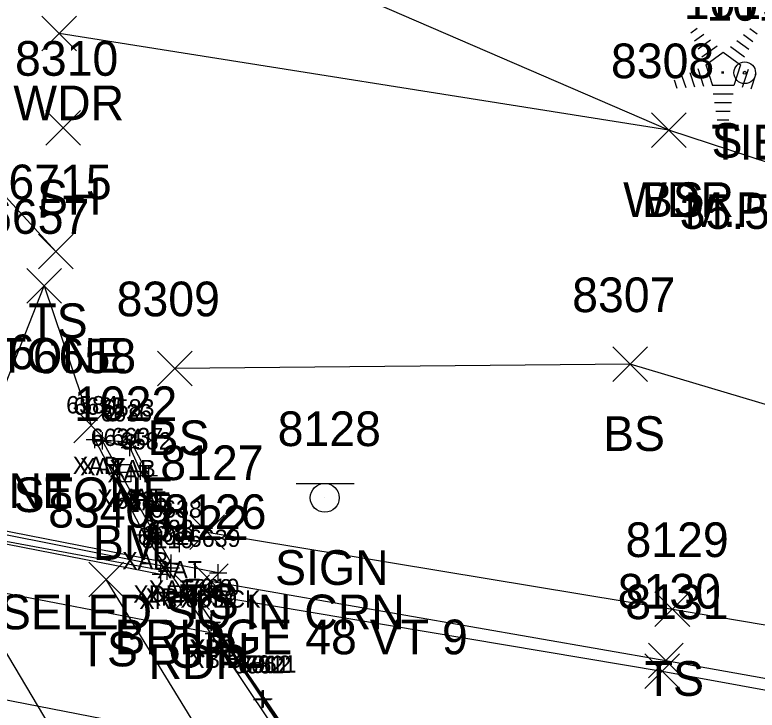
# Model space of a CAD drawing. Extents: x 1588028 to 1589597, y 137576 to 138176.
# Drawn here: x 1588943.52 to 1588986.3, y 137864.66 to 137904.74 of the extents above; entities that cross this region are included whole.
import ezdxf

# ---------------------------------------------------------------- set-up
doc = ezdxf.new("R2010")
doc.units = 0
for name, color, linetype in [('B_A', 7, 'Continuous'), ('B_I', 7, 'Continuous'), ('B_TIC', 7, 'Continuous'), ('BB', 7, 'Continuous'), ('BELB', 7, 'Continuous'), ('BR', 7, 'Continuous'), ('BSE', 7, 'Continuous'), ('BSUBM', 7, 'Continuous'), ('C_A', 7, 'Continuous'), ('C_C', 7, 'Continuous'), ('C_I', 7, 'Continuous'), ('CBP', 7, 'Continuous'), ('CPBM', 7, 'Continuous'), ('L_A', 7, 'Continuous'), ('L_C', 7, 'Continuous'), ('L_I', 7, 'Continuous'), ('L_TIC', 7, 'Continuous'), ('LASF', 7, 'Continuous'), ('LAWA', 7, 'Continuous'), ('LELB', 7, 'Continuous'), ('LTC', 7, 'Continuous'), ('P_A', 7, 'Continuous'), ('P_I', 7, 'Continuous'), ('P_TIC', 7, 'Continuous'), ('PET', 7, 'Continuous'), ('R_A', 7, 'Continuous'), ('R_I', 7, 'Continuous'), ('R_TIC', 7, 'Continuous'), ('RGR', 7, 'Continuous'), ('S_A', 7, 'Continuous'), ('S_C', 7, 'Continuous'), ('S_I', 7, 'Continuous'), ('SSGN', 7, 'Continuous')]:
    doc.layers.add(name, color=color, linetype=linetype)

msp = doc.modelspace()

# ---------------------------------------------------------------- linework, layer by layer
at = {"layer": 'B_TIC'}
for p, q in [((1588948.14, 137880.267), (1588948.215, 137880.267)), ((1588948.581, 137880.188), (1588948.656, 137880.188)), ((1588950.162, 137879.799), (1588950.238, 137879.799)), ((1588950.248, 137880.086), (1588950.324, 137880.086)), ((1588949.573, 137878.389), (1588949.648, 137878.389)), ((1588950.768, 137878.431), (1588950.843, 137878.431)), ((1588951.243, 137878.184), (1588951.319, 137878.184)), ((1588950.994, 137874.773), (1588951.069, 137874.773)), ((1588953.007, 137874.259), (1588953.083, 137874.259)), ((1588952.54, 137873.137), (1588952.615, 137873.137)), ((1588952.303, 137872.682), (1588952.378, 137872.682)), ((1588952.515, 137872.865), (1588952.59, 137872.865)), ((1588955.234, 137872.573), (1588955.31, 137872.573)), ((1588951.934, 137872.493), (1588952.009, 137872.493)), ((1588954.832, 137869.716), (1588954.907, 137869.716)), ((1588954.882, 137869.737), (1588954.958, 137869.737)), ((1588954.995, 137869.089), (1588955.071, 137869.089)), ((1588957.777, 137865.279), (1588957.853, 137865.279)), ((1588957.804, 137865.297), (1588957.879, 137865.297)), ((1588957.828, 137865.308), (1588957.903, 137865.308)), ((1588957.85, 137865.324), (1588957.926, 137865.324))]:
    msp.add_line(p, q, dxfattribs=at)
for points in [[(1588948.136, 137879.767), (1588948.136, 137880.767)], [(1588948.577, 137879.688), (1588948.577, 137880.688)], [(1588947.636, 137880.267), (1588948.636, 137880.267)], [(1588950.159, 137879.299), (1588950.159, 137880.299)], [(1588950.245, 137879.586), (1588950.245, 137880.586)], [(1588948.077, 137880.188), (1588949.077, 137880.188)], [(1588949.659, 137879.799), (1588950.659, 137879.799)], [(1588949.745, 137880.086), (1588950.745, 137880.086)], [(1588950.764, 137877.931), (1588950.764, 137878.931)], [(1588949.569, 137877.889), (1588949.569, 137878.889)], [(1588951.24, 137877.684), (1588951.24, 137878.684)], [(1588949.069, 137878.389), (1588950.069, 137878.389)], [(1588950.264, 137878.431), (1588951.264, 137878.431)], [(1588950.74, 137878.184), (1588951.74, 137878.184)], [(1588950.99, 137874.273), (1588950.99, 137875.273)], [(1588950.49, 137874.773), (1588951.49, 137874.773)], [(1588953.004, 137873.759), (1588953.004, 137874.759)], [(1588952.504, 137874.259), (1588953.504, 137874.259)], [(1588952.536, 137872.637), (1588952.536, 137873.637)], [(1588951.93, 137871.993), (1588951.93, 137872.993)], [(1588952.036, 137873.137), (1588953.036, 137873.137)], [(1588952.299, 137872.182), (1588952.299, 137873.182)], [(1588952.511, 137872.365), (1588952.511, 137873.365)], [(1588955.231, 137872.073), (1588955.231, 137873.073)], [(1588951.799, 137872.682), (1588952.799, 137872.682)], [(1588952.011, 137872.865), (1588953.011, 137872.865)], [(1588954.731, 137872.573), (1588955.731, 137872.573)], [(1588951.43, 137872.493), (1588952.43, 137872.493)], [(1588954.828, 137869.216), (1588954.828, 137870.216)], [(1588954.879, 137869.237), (1588954.879, 137870.237)], [(1588954.328, 137869.716), (1588955.328, 137869.716)], [(1588954.379, 137869.737), (1588955.379, 137869.737)], [(1588954.992, 137868.589), (1588954.992, 137869.589)], [(1588954.492, 137869.089), (1588955.492, 137869.089)], [(1588957.774, 137864.779), (1588957.774, 137865.779)], [(1588957.8, 137864.797), (1588957.8, 137865.797)], [(1588957.824, 137864.808), (1588957.824, 137865.808)], [(1588957.847, 137864.824), (1588957.847, 137865.824)], [(1588957.274, 137865.279), (1588958.274, 137865.279)], [(1588957.3, 137865.297), (1588958.3, 137865.297)], [(1588957.324, 137865.308), (1588958.324, 137865.308)], [(1588957.347, 137865.324), (1588958.347, 137865.324)]]:
    msp.add_lwpolyline(points, dxfattribs=at)
at = {"layer": 'BB'}
for points in [[(1588954.992, 137869.089), (1588908.241, 137878.076)], [(1588959.799, 137861.973), (1588912.85, 137871.124)]]:
    msp.add_lwpolyline(points, dxfattribs=at)
at = {"layer": 'BELB'}
for points in [[(1588955.231, 137872.573), (1588902.634, 137882.887)], [(1588952.511, 137872.865), (1588903.559, 137882.636)]]:
    msp.add_lwpolyline(points, dxfattribs=at)
at = {"layer": 'BR'}
for points in [[(1588903.078, 137882.159), (1588924.609, 137877.821), (1588952.299, 137872.682)], [(1588905.255, 137881.675), (1588928.151, 137877.145), (1588951.93, 137872.493)]]:
    msp.add_lwpolyline(points, dxfattribs=at)
at = {"layer": 'BSE'}
for points in [[(1588954.879, 137869.737), (1588954.828, 137869.716)], [(1588954.828, 137869.716), (1588957.8, 137865.297), (1588957.774, 137865.279), (1588962.554, 137858.252), (1588962.529, 137858.2), (1588967.182, 137851.34), (1588967.162, 137851.326), (1588971.838, 137844.422), (1588971.841, 137844.377), (1588975.126, 137839.692)], [(1588954.879, 137869.737), (1588957.847, 137865.324), (1588957.824, 137865.308), (1588962.604, 137858.282), (1588962.578, 137858.229), (1588967.235, 137851.37), (1588967.22, 137851.341), (1588971.884, 137844.455), (1588971.901, 137844.414), (1588975.167, 137839.727)]]:
    msp.add_lwpolyline(points, dxfattribs=at)
at = {"layer": 'BSUBM'}
for points in [[(1588951.24, 137878.184), (1588950.245, 137880.086), (1588948.136, 137880.267), (1588950.99, 137874.773), (1588976.922, 137836.077), (1588981.762, 137829.017), (1588983.919, 137829.058), (1588980.935, 137832.981)], [(1588952.536, 137873.137), (1588949.569, 137878.389), (1588948.577, 137880.188), (1588950.159, 137879.799), (1588950.764, 137878.431), (1588953.004, 137874.259)]]:
    msp.add_lwpolyline(points, dxfattribs=at)
at = {"layer": 'CBP'}
for radius in [0.625, 0.0833]:
    msp.add_circle((1588985.581, 137901.401), radius, dxfattribs=at)
at = {"layer": 'CPBM'}
for p, q in [((1588949.203, 137877.821), (1588949.203, 137878.821)), ((1588949.203, 137878.821), (1588950.203, 137878.821)), ((1588950.203, 137878.821), (1588950.203, 137877.821)), ((1588949.705, 137878.322), (1588949.705, 137878.322)), ((1588949.705, 137878.322), (1588949.705, 137878.322)), ((1588950.203, 137877.821), (1588949.203, 137877.821))]:
    msp.add_line(p, q, dxfattribs=at)
at = {"layer": 'L_TIC'}
for points in [[(1588945.071, 137902.665), (1588947.071, 137904.665)], [(1588947.071, 137902.665), (1588945.071, 137904.665)], [(1588945.314, 137897.227), (1588947.314, 137899.227)], [(1588947.314, 137897.227), (1588945.314, 137899.227)], [(1588980.214, 137897.085), (1588982.214, 137899.085)], [(1588982.214, 137897.085), (1588980.214, 137899.085)], [(1588980.214, 137897.085), (1588982.214, 137899.085)], [(1588982.214, 137897.085), (1588980.214, 137899.085)], [(1588944.892, 137890.105), (1588946.892, 137892.105)], [(1588946.892, 137890.105), (1588944.892, 137892.105)], [(1588944.219, 137888.116), (1588946.219, 137890.116)], [(1588946.219, 137888.116), (1588944.219, 137890.116)], [(1588951.736, 137883.363), (1588953.736, 137885.363)], [(1588953.736, 137883.363), (1588951.736, 137885.363)], [(1588977.979, 137883.602), (1588979.979, 137885.602)], [(1588979.979, 137883.602), (1588977.979, 137885.602)], [(1588946.914, 137880.079), (1588948.914, 137882.079)], [(1588948.914, 137880.079), (1588946.914, 137882.079)], [(1588953.599, 137873.922), (1588955.599, 137875.922)], [(1588955.599, 137873.922), (1588953.599, 137875.922)], [(1588947.788, 137871.187), (1588949.788, 137873.187)], [(1588949.788, 137871.187), (1588947.788, 137873.187)], [(1588980.412, 137869.487), (1588982.412, 137871.487)], [(1588982.412, 137869.487), (1588980.412, 137871.487)]]:
    msp.add_lwpolyline(points, dxfattribs=at)
at = {"layer": 'LASF'}
for points in [[(1588938.518, 137875.567), (1588942.12, 137881.309), (1588945.219, 137889.116), (1588947.914, 137881.079)], [(1588956.515, 137845.255), (1588938.518, 137875.567)]]:
    msp.add_lwpolyline(points, dxfattribs=at)
at = {"layer": 'LAWA'}
msp.add_lwpolyline([(1588979.127, 137929.799), (1588992.376, 137923.417), (1589010.557, 137910.152), (1589033.478, 137893.69), (1589028.708, 137887.383), (1589019.115, 137885.668), (1588981.214, 137898.085), (1588946.071, 137903.665)], dxfattribs=at)
at = {"layer": 'LELB'}
for points in [[(1588981.214, 137898.085), (1588942.509, 137914.83)], [(1588945.892, 137891.105), (1588931.552, 137906.749)], [(1589071.748, 137862.393), (1589034.865, 137870.653), (1589008.968, 137875.68), (1588978.979, 137884.602), (1588952.736, 137884.363)], [(1588954.599, 137874.922), (1588981.412, 137870.487), (1589021.847, 137863.644), (1589055.492, 137857.051), (1589090.034, 137851.347)], [(1588969.629, 137838.193), (1588948.788, 137872.187)]]:
    msp.add_lwpolyline(points, dxfattribs=at)
at = {"layer": 'LTC'}
for p, q in [((1588982.48, 137903.709), (1588982.835, 137903.967)), ((1588985.879, 137903.95), (1588986.298, 137903.645)), ((1588982.69, 137903.244), (1588983.219, 137903.628)), ((1588985.507, 137903.601), (1588986.057, 137903.202)), ((1588982.899, 137902.778), (1588983.603, 137903.289)), ((1588983.109, 137902.312), (1588983.987, 137902.95)), ((1588984.765, 137902.905), (1588985.575, 137902.316)), ((1588985.136, 137903.253), (1588985.816, 137902.759)), ((1588983.334, 137901.857), (1588984.345, 137902.592)), ((1588984.345, 137902.592), (1588985.342, 137901.867)), ((1588982.879, 137901.638), (1588983.21, 137900.619)), ((1588983.334, 137901.857), (1588983.721, 137900.664)), ((1588985.342, 137901.867), (1588984.951, 137900.664)), ((1588981.968, 137901.205), (1588982.18, 137900.554)), ((1588982.424, 137901.422), (1588982.695, 137900.586)), ((1588985.78, 137901.596), (1588985.442, 137900.556)), ((1588986.224, 137901.346), (1588985.937, 137900.461)), ((1588981.513, 137900.989), (1588981.665, 137900.521)), ((1588984.951, 137900.664), (1588983.721, 137900.664)), ((1588984.913, 137900.164), (1588983.768, 137900.164)), ((1588984.829, 137899.664), (1588983.841, 137899.664)), ((1588984.745, 137899.164), (1588983.914, 137899.164)), ((1588984.661, 137898.664), (1588983.986, 137898.664))]:
    msp.add_line(p, q, dxfattribs=at)
at = {"layer": 'P_TIC'}
for points in [[(1588952.737, 137870.461), (1588954.737, 137872.461)], [(1588954.737, 137870.461), (1588952.737, 137872.461)], [(1588979.824, 137865.908), (1588981.824, 137867.908)], [(1588981.824, 137865.908), (1588979.824, 137867.908)]]:
    msp.add_lwpolyline(points, dxfattribs=at)
at = {"layer": 'PET'}
msp.add_lwpolyline([(1588976.423, 137837.983), (1588964.714, 137855.4), (1588953.737, 137871.461), (1588980.824, 137866.908), (1589021.21, 137859.548), (1589054.577, 137852.925), (1589087.364, 137843.769), (1589127.637, 137831.447), (1589150.053, 137824.373), (1589196.141, 137808.721), (1589243.873, 137790.956), (1589276.872, 137778.078), (1589322.252, 137759.621), (1589367.819, 137740.822), (1589401.867, 137726.111), (1589432.806, 137712.852), (1589459.757, 137701.463)], dxfattribs=at)
at = {"layer": 'R_TIC'}
for points in [[(1588953.82, 137871.101), (1588955.82, 137873.101)], [(1588955.82, 137871.101), (1588953.82, 137873.101)], [(1588980.044, 137866.516), (1588982.044, 137868.516)], [(1588982.044, 137866.516), (1588980.044, 137868.516)]]:
    msp.add_lwpolyline(points, dxfattribs=at)
at = {"layer": 'RGR'}
msp.add_lwpolyline([(1588954.82, 137872.101), (1588981.044, 137867.516), (1589021.549, 137860.281), (1589054.778, 137853.826), (1589090.795, 137848.762)], dxfattribs=at)
at = {"layer": 'SSGN'}
for p, q in [((1588959.735, 137877.735), (1588963.068, 137877.735)), ((1588961.382, 137876.902), (1588961.382, 137876.902))]:
    msp.add_line(p, q, dxfattribs=at)
msp.add_circle((1588961.382, 137876.902), 0.833, dxfattribs=at)

# ---------------------------------------------------------------- texts
at = {"layer": 'B_A'}
for s, p in [('XAB', (1588946.857, 137878.267)), ('XAT', (1588947.282, 137878.188)), ('XAB', (1588948.965, 137878.086)), ('XAT', (1588948.863, 137877.799)), ('XAT', (1588948.274, 137876.389)), ('XAT', (1588949.469, 137876.431)), ('XAB', (1588949.96, 137876.184)), ('XAB', (1588949.711, 137872.773)), ('XAT', (1588951.708, 137872.259)), ('XAT', (1588951.241, 137871.137)), ('XDECK', (1588950.354, 137870.865)), ('XRF', (1588951.059, 137870.682)), ('XRF', (1588950.69, 137870.493)), ('XDECK', (1588953.073, 137870.573)), ('XBS', (1588953.569, 137867.716)), ('XBS', (1588953.619, 137867.737)), ('XBIB', (1588953.563, 137867.089))]:
    msp.add_text(s, height=1, dxfattribs=at).set_placement(p)
at = {"layer": 'B_I'}
for s, p in [('6584', (1588946.482, 137881.767)), ('6635', (1588946.9, 137881.688)), ('6583', (1588948.591, 137881.586)), ('6636', (1588948.454, 137881.299)), ('6634', (1588947.892, 137879.889)), ('6637', (1588949.087, 137879.931)), ('6582', (1588949.586, 137879.684)), ('6585', (1588949.337, 137876.273)), ('6638', (1588951.326, 137875.759)), ('6633', (1588950.859, 137874.637)), ('6602', (1588950.583, 137874.182)), ('8381', (1588951.165, 137874.365)), ('6639', (1588953.55, 137874.073)), ('8110', (1588950.824, 137873.993)), ('6660', (1588953.084, 137871.216)), ('7910', (1588953.489, 137871.237)), ('8339', (1588953.358, 137870.589)), ('6661', (1588956.383, 137866.797)), ('7912', (1588956.478, 137866.808)), ('7911', (1588956.784, 137866.824)), ('6662', (1588956.073, 137866.779))]:
    msp.add_text(s, height=1, dxfattribs=at).set_placement(p)
at = {"layer": 'C_A'}
for s, p in [('TIE', (1588983.66, 137896.401)), ('BM', (1588948.02, 137873.322))]:
    msp.add_text(s, height=2, dxfattribs=at).set_placement(p)
at = {"layer": 'C_C'}
for s, p in [('35.52', (1588981.833, 137892.401)), ('BM #2 ... CHISELED SQ IN CRN', (1588926.611, 137869.322))]:
    msp.add_text(s, height=2, dxfattribs=at).set_placement(p)
at = {"layer": 'C_I'}
for s, p in [('1018', (1588983.376, 137904.401)), ('1022', (1588946.933, 137881.322))]:
    msp.add_text(s, height=2, dxfattribs=at).set_placement(p)
at = {"layer": 'L_A'}
for s, p in [('WDR', (1588943.433, 137898.665)), ('S', (1588983.671, 137896.501)), ('SH', (1588944.802, 137893.227)), ('WDR', (1588978.576, 137893.085)), ('BS', (1588979.655, 137893.085)), ('TS', (1588944.302, 137886.105)), ('STONE', (1588940.763, 137884.116)), ('BS', (1588977.42, 137879.602)), ('BS', (1588951.177, 137879.363)), ('STONE', (1588937.664, 137876.309)), ('STONE', (1588943.457, 137876.079)), ('TS', (1588953.008, 137869.922)), ('TS', (1588947.198, 137867.187)), ('TS', (1588979.821, 137865.487))]:
    msp.add_text(s, height=2, dxfattribs=at).set_placement(p)
at = {"layer": 'L_C'}
msp.add_text('M.P', height=2, dxfattribs=at).set_placement((1588982.104, 137892.501))
at = {"layer": 'L_I'}
for s, p in [('1019', (1588982.072, 137904.501)), ('8310', (1588943.534, 137901.227)), ('8308', (1588977.875, 137901.085)), ('8308', (1588977.875, 137901.085)), ('6715', (1588943.152, 137894.105)), ('6657', (1588941.865, 137892.116)), ('8307', (1588975.64, 137887.602)), ('8309', (1588949.39, 137887.363)), ('6656', (1588938.711, 137884.309)), ('6658', (1588944.56, 137884.079)), ('8127', (1588951.906, 137877.922)), ('8340', (1588945.442, 137875.187)), ('8129', (1588978.711, 137873.487))]:
    msp.add_text(s, height=2, dxfattribs=at).set_placement(p)
at = {"layer": 'LTC'}
msp.add_text('.', height=1.037, rotation=270, dxfattribs=at).set_placement((1588984.228, 137901.605))
at = {"layer": 'P_A'}
msp.add_text('RDP', height=2, dxfattribs=at).set_placement((1588951.225, 137866.461))
at = {"layer": 'P_I'}
for s, p in [('8122', (1588951.044, 137874.461)), ('8131', (1588978.698, 137869.908))]:
    msp.add_text(s, height=2, dxfattribs=at).set_placement(p)
at = {"layer": 'R_A'}
msp.add_text('GRL', height=2, dxfattribs=at).set_placement((1588952.363, 137867.101))
at = {"layer": 'R_I'}
for s, p in [('8126', (1588952.072, 137875.101)), ('8130', (1588978.264, 137870.516))]:
    msp.add_text(s, height=2, dxfattribs=at).set_placement(p)
at = {"layer": 'S_A'}
msp.add_text('SIGN', height=2, dxfattribs=at).set_placement((1588958.52, 137871.882))
at = {"layer": 'S_C'}
msp.add_text('BRIDGE 48 VT 9', height=2, dxfattribs=at).set_placement((1588949.26, 137867.882))
at = {"layer": 'S_I'}
msp.add_text('8128', height=2, dxfattribs=at).set_placement((1588958.669, 137879.882))

doc.saveas('drawing.dxf')
